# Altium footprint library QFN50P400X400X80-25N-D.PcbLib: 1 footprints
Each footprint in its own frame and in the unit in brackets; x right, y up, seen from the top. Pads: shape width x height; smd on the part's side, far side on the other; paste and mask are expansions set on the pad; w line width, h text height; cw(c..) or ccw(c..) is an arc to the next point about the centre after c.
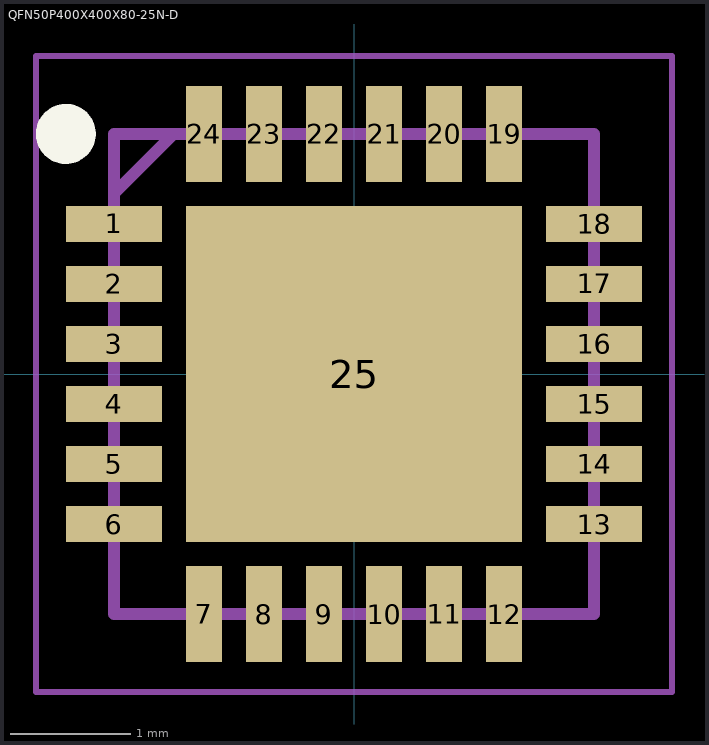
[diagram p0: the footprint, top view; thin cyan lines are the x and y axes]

## QFN50P400X400X80-25N-D [mm]
pads (25):
  rect 0.8x0.3 smd: 1(-2,1.25) 2(-2,0.75) 3(-2,0.25) 4(-2,-0.25) 5(-2,-0.75) 6(-2,-1.25) 13(2,-1.25) 14(2,-0.75) 15(2,-0.25) 16(2,0.25) 17(2,0.75) 18(2,1.25)
  rect 0.3x0.8 smd: 7(-1.25,-2) 8(-0.75,-2) 9(-0.25,-2) 10(0.25,-2) 11(0.75,-2) 12(1.25,-2) 19(1.25,2) 20(0.75,2) 21(0.25,2) 22(-0.25,2) 23(-0.75,2) 24(-1.25,2)
  rect 2.8x2.8 smd: 25(0,0)
Top Overlay:
  circle w0.25: c-2.4,2 r0.125
Mechanical 15:
  lines w0.1: -2,1.5 -1.5,2 ; -2,-2 2,-2 2,2 -2,2 -2,-2
Mechanical 20:
  lines w0.05: -2.65,-2.65 2.65,-2.65 2.65,2.65 -2.65,2.65 -2.65,-2.65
